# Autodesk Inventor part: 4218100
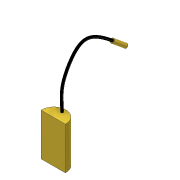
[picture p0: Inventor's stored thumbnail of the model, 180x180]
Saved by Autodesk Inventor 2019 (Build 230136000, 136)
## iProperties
Created: 2020-12
Part Number: 4218100
Material: Wood (Birch)
Document SubType Name: Modeling
Designer: user
Density: 0.55 g/cm^3
Appearance: Birch - Natural Polished
Author: user
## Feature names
1. Extrusion1
2. Extrusion2
3. Sweep1
4. Extrusion3
5. Extrusion4
## Parameters: d6 = 0, d7 = 12 mm, d12 = 466 mm, d15 = 0, d16 = 0, d17 = 0, d18 = 15 mm, d19 = 75 mm, d20 = 0, d21 = 75 mm, d22 = 0
